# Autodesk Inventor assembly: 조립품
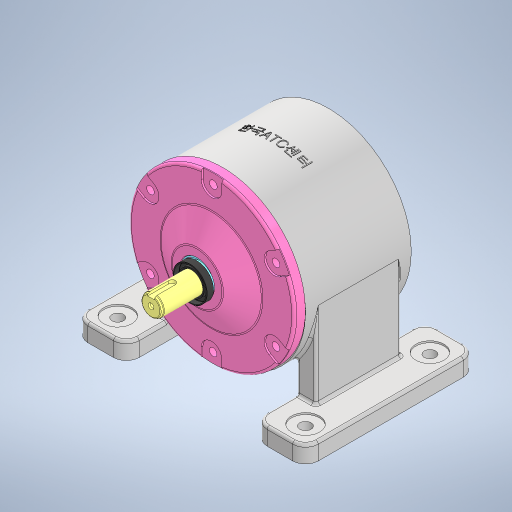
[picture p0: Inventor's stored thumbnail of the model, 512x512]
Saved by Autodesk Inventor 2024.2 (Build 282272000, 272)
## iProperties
Created: 2025-12
Part Number: 조립품
Document SubType Name: Assembly
Designer: home
Author: home
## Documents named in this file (15)
- C:\Users\home\Documents\Inventor\751203V1013\조립품.iam
- C:\Users\home\Documents\Inventor\751203V1013\본체.ipt
- C:\Users\home\Desktop\750903V1008\칼라 1\칼라 1.ipt
- C:\Users\home\Desktop\750903V1008\출력 축\출력 축.ipt
- C:\Users\home\Desktop\750903V1008\종동 기어\종동 기어.ipt
- C:\Users\home\Desktop\750903V1008\오일 실 25 40 8\오일 실 25 40 8.ipt
- C:\Users\home\Desktop\750903V1008\엔드 캡\엔드 캡.ipt
- C:\Users\home\Desktop\750903V1008\깊은 홈 볼 베어링 6005\깊은 홈 볼 베어링 6005.ipt
- C:\Users\home\Desktop\750903V1008\깊은 홈 볼 베어링 6004\깊은 홈 볼 베어링 6004.ipt
- C:\Users\home\Desktop\750903V1008\기어 축\기어 축.ipt
- C:\Users\home\Desktop\750903V1008\구동 기어\구동 기어.ipt
- C:\Users\home\Desktop\750903V1008\C형 멈춤링 구멍용 42\C형 멈춤링 구멍용 42.ipt
- C:\Users\home\Desktop\750903V1008\6각 머리 볼트 M8x20\6각 머리 볼트 M8x20.ipt
- C:\Users\home\Documents\Inventor\751203V1013\평행 키 6x6x16\평행 키 6x6x16.ipt
- C:\Users\home\Documents\Inventor\751203V1013\커버\커버.ipt
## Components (3 placed, 3 different names)
1. 구동 기어:1
2. C형 멈춤링 구멍용 42:1
3. 6각 머리 볼트 M8x20:1
